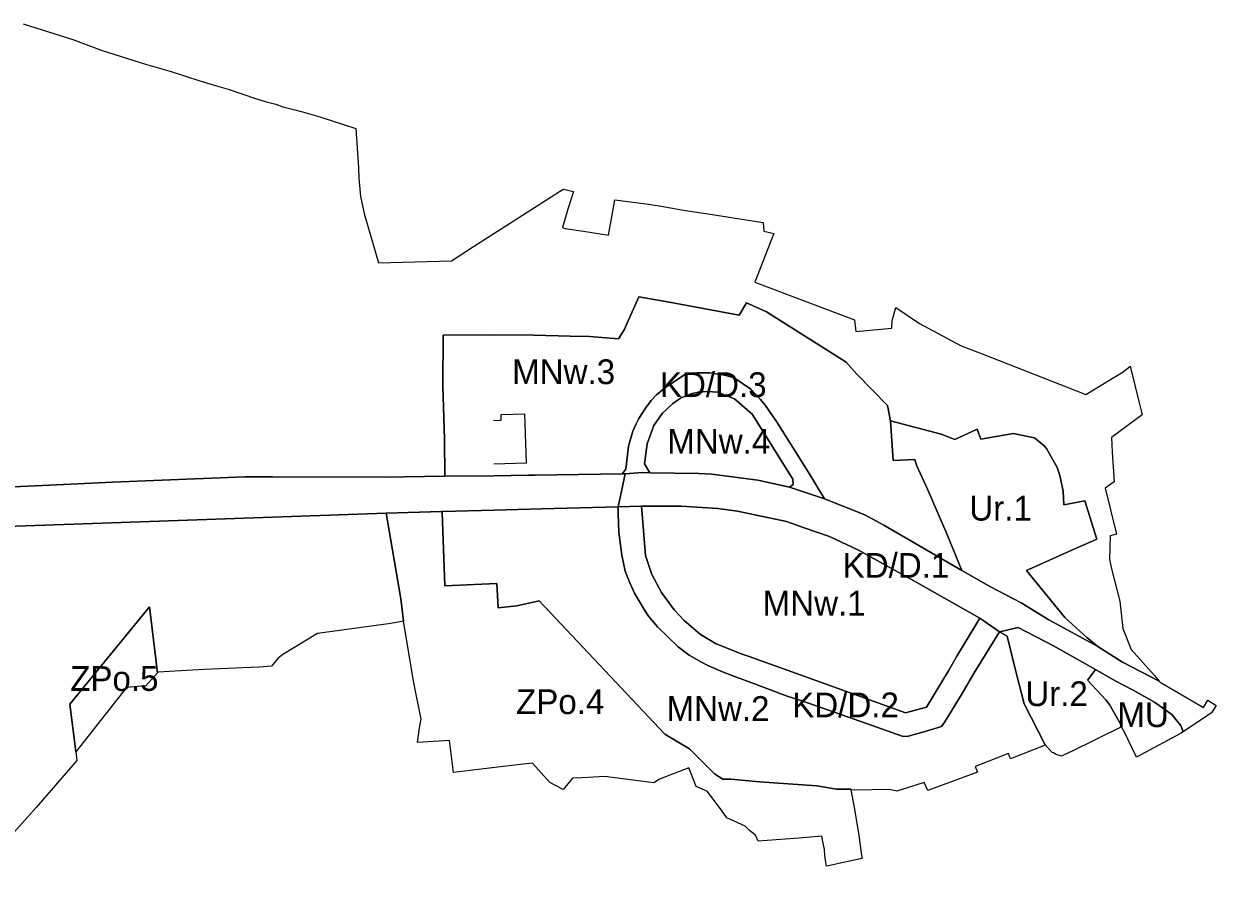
# Model space of a CAD drawing. Extents: x 7418114 to 7422197, y 5546299 to 5548348.
# Drawn here: x 7421715.4 to 7422197, y 5546763.3 to 5547110.1 of the extents above; entities that cross this region are included whole.
import ezdxf

# ---------------------------------------------------------------- set-up
doc = ezdxf.new("R2010")
doc.units = 0
for name, color, linetype in [('linie_rozgraniczajace', 7, 'Continuous'), ('linie_zabudowy_nieprzekraczalne', 7, 'Continuous'), ('oznaczenia_przeznaczen', 7, 'Continuous')]:
    doc.layers.add(name, color=color, linetype=linetype)

msp = doc.modelspace()

# ---------------------------------------------------------------- linework, layer by layer
at = {"layer": 'linie_rozgraniczajace'}
for points in [[(7421715.19, 5547110.07), (7421735.26, 5547103.68), (7421747.03, 5547099.34), (7421764.54, 5547093.8), (7421774.97, 5547090.79), (7421780.67, 5547088.99), (7421786.52, 5547087.08), (7421792.25, 5547085.24), (7421798.03, 5547083.67), (7421803.83, 5547081.68), (7421808.99, 5547079.88), (7421812.1, 5547078.95), (7421813.49, 5547078.58), (7421817.24, 5547077.57), (7421820.04, 5547076.58), (7421824.91, 5547075.26), (7421827.94, 5547074.48), (7421833.69, 5547072.95), (7421835.44, 5547072.38), (7421844.54, 5547069.37), (7421849.52, 5547067.79), (7421850.55, 5547051.83), (7421850.77, 5547047.76), (7421851.41, 5547040.3), (7421852.86, 5547033.4), (7421858.74, 5547013.44), (7421888.2, 5547014.28), (7421897.07, 5547020.04)], [(7421897.07, 5547020.04), (7421911.62, 5547029.42), (7421931.86, 5547042.32), (7421933.39, 5547043.29), (7421937.49, 5547042.38), (7421936.43, 5547038.94), (7421935.17, 5547035.15), (7421933, 5547027.75), (7421934.1, 5547027.4), (7421941.55, 5547026.29), (7421951.54, 5547024.62), (7421952.9, 5547032.08), (7421954.14, 5547038.9), (7421967.7, 5547037.24), (7421972.82, 5547036.39), (7421982.68, 5547034.62), (7421992.7, 5547033.12), (7422014.12, 5547029.86), (7422014.37, 5547026.28), (7422018.44, 5547025.37), (7422015.9, 5547019.13), (7422010.73, 5547005.69), (7422051.01, 5546990.53), (7422051.52, 5546985.79), (7422065.98, 5546987.12), (7422066.17, 5546990.19), (7422067.67, 5546995.47), (7422077.27, 5546988.94), (7422094.05, 5546979.99), (7422102.49, 5546976.78), (7422144.36, 5546960.37), (7422159.45, 5546969.45), (7422162.35, 5546971.73), (7422166.07, 5546956.41), (7422167.16, 5546952.08), (7422154.72, 5546942.96), (7422155.09, 5546937.03), (7422155.79, 5546925.05), (7422152.15, 5546922.44), (7422156.85, 5546903.88), (7422154.17, 5546903.2), (7422153.9, 5546893.59), (7422154.96, 5546889.37), (7422158.12, 5546876.77), (7422159.36, 5546865.74), (7422162.76, 5546857.26), (7422172.17, 5546846.8), (7422174.04, 5546844.51), (7422159.21, 5546852.2), (7422157.05, 5546853.55), (7422149.22, 5546858.49), (7422144.87, 5546862.15), (7422135.86, 5546870.24), (7422120.42, 5546889.14), (7422140.23, 5546898.1), (7422148.84, 5546901.92), (7422144.06, 5546917.41), (7422135.53, 5546915.66), (7422135.19, 5546921.31), (7422133.87, 5546927.64), (7422132.8, 5546930.77), (7422128.54, 5546938.52), (7422127.52, 5546939.58), (7422123.71, 5546942.81), (7422114.99, 5546944.51), (7422102, 5546942.21), (7422100.45, 5546946.35), (7422091.48, 5546942.18), (7422085.94, 5546944.22), (7422065.54, 5546949.61), (7422064.29, 5546955.86), (7422051.86, 5546968.57), (7422047.66, 5546973.4), (7422015.45, 5546993.74), (7422007.31, 5546997.33), (7422004.42, 5546992.34), (7421976.93, 5546997.45), (7421963.83, 5546999.72), (7421957.96, 5546986.4), (7421955.65, 5546982.86), (7421943.87, 5546983.7), (7421936.15, 5546983.89), (7421921.42, 5546984.29), (7421905.01, 5546984.42), (7421884.8, 5546984.3), (7421884.71, 5546963.86), (7421885.39, 5546942.06), (7421885.53, 5546927.25), (7421861, 5546926.89), (7421815.86, 5546926.99), (7421811.95, 5546927), (7421804.71, 5546927.01), (7421751.26, 5546924.91), (7421723.02, 5546923.6), (7421666.87, 5546920.97)], [(7421666.87, 5546920.97), (7421723.02, 5546923.6), (7421751.26, 5546924.91), (7421804.71, 5546927.01), (7421811.95, 5546927), (7421815.86, 5546926.99), (7421861, 5546926.89), (7421885.53, 5546927.25), (7421905.32, 5546927.49), (7421919.22, 5546927.66), (7421921.92, 5546927.77), (7421957.06, 5546928.27), (7421958.26, 5546928.29), (7421955.48, 5546914.95), (7421924.59, 5546914.1), (7421905.44, 5546913.59), (7421884.55, 5546913.01), (7421884.13, 5546913), (7421861.75, 5546912.42), (7421762.38, 5546908.91), (7421681.35, 5546906.04)], [(7421681.35, 5546906.04), (7421762.38, 5546908.91), (7421861.75, 5546912.42), (7421867.69, 5546877.79), (7421868.77, 5546868.77), (7421863.64, 5546867.76), (7421834.05, 5546863.7), (7421819.99, 5546855.19), (7421818, 5546853.69), (7421815.41, 5546850.55), (7421810.4, 5546850.09), (7421788.3, 5546849.19), (7421774.14, 5546848.4), (7421769.64, 5546848.17), (7421769.36, 5546847.85), (7421766.21, 5546874.51), (7421749.24, 5546853.73), (7421734.08, 5546835.17), (7421736.3, 5546817.18), (7421736.42, 5546815.98), (7421736.78, 5546812.38), (7421720.39, 5546793.42), (7421693.4, 5546763.27)]]:
    msp.add_lwpolyline(points, dxfattribs=at)
for points in [[(7421885.53, 5546927.25), (7421885.39, 5546942.06), (7421884.71, 5546963.86), (7421884.8, 5546984.3), (7421905.01, 5546984.42), (7421921.42, 5546984.29), (7421936.15, 5546983.89), (7421943.87, 5546983.7), (7421955.65, 5546982.86), (7421957.96, 5546986.4), (7421963.83, 5546999.72), (7421976.93, 5546997.45), (7422004.42, 5546992.34), (7422007.31, 5546997.33), (7422015.45, 5546993.74), (7422047.66, 5546973.4), (7422051.86, 5546968.57), (7422064.29, 5546955.86), (7422065.54, 5546949.61), (7422066.59, 5546933.64), (7422075.28, 5546933.99), (7422076.07, 5546931.82), (7422080.42, 5546922.07), (7422088.24, 5546904.05), (7422094.35, 5546889.13), (7422062.85, 5546907.46), (7422055.07, 5546911.65), (7422038.9, 5546918.1), (7422034.98, 5546924.58), (7422032.22, 5546929.09), (7422019.52, 5546949.34), (7422014.85, 5546955.96), (7422013.03, 5546958.33), (7422009.08, 5546962.43), (7422002.39, 5546967.06), (7421998.44, 5546968.14), (7421992.36, 5546969.05), (7421987.29, 5546969.05), (7421982.32, 5546968.25), (7421974.74, 5546963.27), (7421971, 5546960.21), (7421968.81, 5546957.94), (7421966.49, 5546954.77), (7421963.82, 5546950.58), (7421962.74, 5546948.45), (7421961.43, 5546945.48), (7421959.74, 5546939.4), (7421958.58, 5546930.2), (7421957.06, 5546928.27), (7421921.92, 5546927.77), (7421919.22, 5546927.66), (7421905.32, 5546927.49)], [(7421957.06, 5546928.27), (7421958.58, 5546930.2), (7421959.74, 5546939.4), (7421961.43, 5546945.48), (7421962.74, 5546948.45), (7421963.82, 5546950.58), (7421966.49, 5546954.77), (7421968.81, 5546957.94), (7421971, 5546960.21), (7421974.74, 5546963.27), (7421982.32, 5546968.25), (7421987.29, 5546969.05), (7421992.36, 5546969.05), (7421998.44, 5546968.14), (7422002.39, 5546967.06), (7422009.08, 5546962.43), (7422013.03, 5546958.33), (7422014.85, 5546955.96), (7422019.52, 5546949.34), (7422032.22, 5546929.09), (7422034.98, 5546924.58), (7422038.9, 5546918.1), (7422024.69, 5546922.93), (7422026.25, 5546923.99), (7422026.07, 5546926.09), (7422009.59, 5546952.34), (7422002.43, 5546958.55), (7421995.56, 5546961.19), (7421991.65, 5546961.53), (7421987.84, 5546961.29), (7421985.03, 5546960.56), (7421980.67, 5546958.82), (7421977.41, 5546956.52), (7421973.25, 5546952.57), (7421969.94, 5546947.73), (7421967.24, 5546940.31), (7421966.1, 5546932.3), (7421968.33, 5546928.7), (7421965.2, 5546928.74), (7421958.26, 5546928.29)], [(7421966.1, 5546932.3), (7421967.24, 5546940.31), (7421969.94, 5546947.73), (7421973.25, 5546952.57), (7421977.41, 5546956.52), (7421980.67, 5546958.82), (7421985.03, 5546960.56), (7421987.84, 5546961.29), (7421991.65, 5546961.53), (7421995.56, 5546961.19), (7422002.43, 5546958.55), (7422009.59, 5546952.34), (7422026.07, 5546926.09), (7422026.25, 5546923.99), (7422024.69, 5546922.93), (7422011.87, 5546925.71), (7421993.36, 5546928.16), (7421988.14, 5546928.45), (7421968.33, 5546928.7)], [(7422065.54, 5546949.61), (7422085.94, 5546944.22), (7422091.48, 5546942.18), (7422100.45, 5546946.35), (7422102, 5546942.21), (7422114.99, 5546944.51), (7422123.71, 5546942.81), (7422127.52, 5546939.58), (7422128.54, 5546938.52), (7422132.8, 5546930.77), (7422133.87, 5546927.64), (7422135.19, 5546921.31), (7422135.53, 5546915.66), (7422144.06, 5546917.41), (7422148.84, 5546901.92), (7422140.23, 5546898.1), (7422120.42, 5546889.14), (7422135.86, 5546870.24), (7422144.87, 5546862.15), (7422149.22, 5546858.49), (7422129.52, 5546869.21), (7422118.29, 5546876.09), (7422105.89, 5546882.57), (7422094.35, 5546889.13), (7422088.24, 5546904.05), (7422080.42, 5546922.07), (7422076.07, 5546931.82), (7422075.28, 5546933.99), (7422066.59, 5546933.64)], [(7421955.48, 5546914.95), (7421958.26, 5546928.29), (7421965.2, 5546928.74), (7421968.33, 5546928.7), (7421988.14, 5546928.45), (7421993.36, 5546928.16), (7422011.87, 5546925.71), (7422024.69, 5546922.93), (7422038.9, 5546918.1), (7422055.07, 5546911.65), (7422062.85, 5546907.46), (7422094.35, 5546889.13), (7422105.89, 5546882.57), (7422118.29, 5546876.09), (7422129.52, 5546869.21), (7422149.22, 5546858.49), (7422157.05, 5546853.55), (7422159.21, 5546852.2), (7422174.04, 5546844.51), (7422174.36, 5546844.11), (7422191.89, 5546833.82), (7422193.62, 5546836.76), (7422197.04, 5546834.68), (7422195.22, 5546831.64), (7422183.68, 5546824.01), (7422182.73, 5546826.61), (7422181.24, 5546828.3), (7422179.22, 5546830.92), (7422177.28, 5546832.41), (7422176.29, 5546833.08), (7422172.17, 5546835.94), (7422163.52, 5546840.9), (7422156.22, 5546844.6), (7422148.24, 5546849.22), (7422131.28, 5546858.78), (7422117.11, 5546866.21), (7422109.57, 5546864.41), (7422101.54, 5546869.87), (7422076.14, 5546884.34), (7422052.55, 5546897.45), (7422040.91, 5546902.9), (7422030.58, 5546906.39), (7422023.56, 5546908.97), (7422003.72, 5546913.17), (7421995.77, 5546914.26), (7421980.92, 5546915.18), (7421964.98, 5546915.2), (7421964.64, 5546915.2)], [(7421861.75, 5546912.42), (7421884.13, 5546913), (7421884.55, 5546913.01), (7421884.47, 5546912.63), (7421885.46, 5546882.98), (7421906.55, 5546883.91), (7421907.06, 5546874.16), (7421914.57, 5546874.94), (7421923.55, 5546876.97), (7421974.35, 5546823.04), (7421984.29, 5546817.2), (7421994.44, 5546807.03), (7421997.75, 5546804.94), (7422000.96, 5546804.88), (7422012.54, 5546803.79), (7422035.77, 5546802.14), (7422043.73, 5546800.8), (7422049.42, 5546800.89), (7422049.48, 5546800.62), (7422050.78, 5546793.46), (7422052.67, 5546782.21), (7422053.84, 5546774.02), (7422053.99, 5546772.86), (7422050.78, 5546772.18), (7422040.95, 5546770.01), (7422039.64, 5546769.77), (7422039.22, 5546772.22), (7422039.01, 5546774.05), (7422038.78, 5546776.42), (7422038.27, 5546779.06), (7422037.78, 5546781.85), (7422030.24, 5546781.15), (7422012.03, 5546779.86), (7422010.93, 5546782.24), (7422008.6, 5546784.2), (7422006.74, 5546785.85), (7421999.45, 5546789.24), (7421997.27, 5546792.42), (7421993.89, 5546796.85), (7421991.55, 5546799.89), (7421987.03, 5546801.96), (7421984.01, 5546809.46), (7421972.2, 5546804.83), (7421969.94, 5546803.44), (7421954.13, 5546805.43), (7421950.31, 5546805.91), (7421940.79, 5546805.39), (7421937.02, 5546805.31), (7421933.25, 5546800.72), (7421927.89, 5546803.57), (7421920.96, 5546811.4), (7421911.33, 5546810.26), (7421889.05, 5546807.52), (7421887.4, 5546820.54), (7421874.42, 5546819.64), (7421875.28, 5546825.6), (7421875.95, 5546829.15), (7421872.97, 5546843.81), (7421868.77, 5546868.77), (7421867.69, 5546877.79)], [(7421885.46, 5546882.98), (7421884.47, 5546912.63), (7421884.55, 5546913.01), (7421905.44, 5546913.59), (7421924.59, 5546914.1), (7421955.48, 5546914.95), (7421955.51, 5546912.07), (7421955.73, 5546904.65), (7421957, 5546895.33), (7421958.38, 5546888.88), (7421960.23, 5546884.17), (7421962.12, 5546879.99), (7421966.05, 5546873.41), (7421967.81, 5546870.72), (7421971.44, 5546866.44), (7421979.73, 5546858.35), (7421984.2, 5546855.05), (7421989.14, 5546852.18), (7421991.68, 5546850.81), (7421997.69, 5546848.23), (7422002.87, 5546846.25), (7422007.39, 5546844.66), (7422023.76, 5546838.45), (7422030.14, 5546836.34), (7422055.81, 5546827.4), (7422070.17, 5546822.25), (7422072.19, 5546822.18), (7422079.95, 5546824.23), (7422086.04, 5546826.18), (7422087.44, 5546828.03), (7422094.43, 5546839.55), (7422099.34, 5546847.9), (7422109.57, 5546864.41), (7422112.58, 5546862.71), (7422116.34, 5546847.3), (7422119.48, 5546835.31), (7422127.95, 5546818.69), (7422128.02, 5546818.57), (7422114.03, 5546813.04), (7422113.11, 5546815.23), (7422099.7, 5546809.95), (7422100.62, 5546807.77), (7422080.62, 5546800.28), (7422079.1, 5546803.56), (7422068.12, 5546800.05), (7422065.03, 5546800.76), (7422051.14, 5546800.47), (7422049.48, 5546800.62), (7422049.42, 5546800.89), (7422043.73, 5546800.8), (7422035.77, 5546802.14), (7422012.54, 5546803.79), (7422000.96, 5546804.88), (7421997.75, 5546804.94), (7421994.44, 5546807.03), (7421984.29, 5546817.2), (7421974.35, 5546823.04), (7421923.55, 5546876.97), (7421914.57, 5546874.94), (7421907.06, 5546874.16), (7421906.55, 5546883.91)], [(7421955.73, 5546904.65), (7421955.51, 5546912.07), (7421955.48, 5546914.95), (7421964.64, 5546915.2), (7421964.98, 5546915.2), (7421965.19, 5546911.91), (7421966.6, 5546895.21), (7421969.04, 5546887.62), (7421973.03, 5546880.35), (7421978.07, 5546873.3), (7421982.11, 5546868.94), (7421988.77, 5546863.4), (7421995.15, 5546859.51), (7422005.59, 5546855.34), (7422007.96, 5546854.6), (7422025.65, 5546848.25), (7422028.95, 5546847.03), (7422054.12, 5546837.97), (7422071.59, 5546831.72), (7422080.07, 5546833.99), (7422088.96, 5546848.59), (7422092.36, 5546854.54), (7422100, 5546867.3), (7422101.54, 5546869.87), (7422109.57, 5546864.41), (7422099.34, 5546847.9), (7422094.43, 5546839.55), (7422087.44, 5546828.03), (7422086.04, 5546826.18), (7422079.95, 5546824.23), (7422072.19, 5546822.18), (7422070.17, 5546822.25), (7422055.81, 5546827.4), (7422030.14, 5546836.34), (7422023.76, 5546838.45), (7422007.39, 5546844.66), (7422002.87, 5546846.25), (7421997.69, 5546848.23), (7421991.68, 5546850.81), (7421989.14, 5546852.18), (7421984.2, 5546855.05), (7421979.73, 5546858.35), (7421971.44, 5546866.44), (7421967.81, 5546870.72), (7421966.05, 5546873.41), (7421962.12, 5546879.99), (7421960.23, 5546884.17), (7421958.38, 5546888.88), (7421957, 5546895.33)], [(7421964.98, 5546915.2), (7421980.92, 5546915.18), (7421995.77, 5546914.26), (7422003.72, 5546913.17), (7422023.56, 5546908.97), (7422030.58, 5546906.39), (7422040.91, 5546902.9), (7422052.55, 5546897.45), (7422076.14, 5546884.34), (7422101.54, 5546869.87), (7422100, 5546867.3), (7422092.36, 5546854.54), (7422088.96, 5546848.59), (7422080.07, 5546833.99), (7422071.59, 5546831.72), (7422054.12, 5546837.97), (7422028.95, 5546847.03), (7422025.65, 5546848.25), (7422007.96, 5546854.6), (7422005.59, 5546855.34), (7421995.15, 5546859.51), (7421988.77, 5546863.4), (7421982.11, 5546868.94), (7421978.07, 5546873.3), (7421973.03, 5546880.35), (7421969.04, 5546887.62), (7421966.6, 5546895.21), (7421965.19, 5546911.91)], [(7421734.08, 5546835.17), (7421749.24, 5546853.73), (7421766.21, 5546874.51), (7421769.36, 5546847.85), (7421764.67, 5546842.66), (7421756.88, 5546841.97), (7421736.42, 5546815.98), (7421736.3, 5546817.18)], [(7422109.57, 5546864.41), (7422117.11, 5546866.21), (7422131.28, 5546858.78), (7422148.24, 5546849.22), (7422147.97, 5546848.84), (7422147.23, 5546847.76), (7422145.01, 5546844.93), (7422152.42, 5546836.88), (7422154, 5546835.05), (7422155.76, 5546831.92), (7422159.06, 5546826.09), (7422158.85, 5546825.99), (7422158.83, 5546826.02), (7422138.35, 5546815.96), (7422138.3, 5546815.94), (7422138.25, 5546815.91), (7422134.61, 5546814.22), (7422132.36, 5546814.87), (7422131.35, 5546815.56), (7422130.75, 5546815.66), (7422128.13, 5546818.62), (7422128.02, 5546818.57), (7422127.95, 5546818.69), (7422119.48, 5546835.31), (7422116.34, 5546847.3), (7422112.58, 5546862.71)], [(7422145.01, 5546844.93), (7422147.23, 5546847.76), (7422147.97, 5546848.84), (7422148.24, 5546849.22), (7422156.22, 5546844.6), (7422163.52, 5546840.9), (7422172.17, 5546835.94), (7422176.29, 5546833.08), (7422177.28, 5546832.41), (7422179.22, 5546830.92), (7422181.24, 5546828.3), (7422182.73, 5546826.61), (7422183.68, 5546824.01), (7422182.68, 5546823.34), (7422164.9, 5546813.82), (7422159.94, 5546824.18), (7422158.85, 5546825.99), (7422159.06, 5546826.09), (7422155.76, 5546831.92), (7422154, 5546835.05), (7422152.42, 5546836.88)]]:
    msp.add_lwpolyline(points, close=True, dxfattribs=at)
at = {"layer": 'linie_zabudowy_nieprzekraczalne'}
for points in [[(7421905.2, 5546949.85), (7421908.2, 5546949.93), (7421908.19, 5546952.07)], [(7421917.83, 5546952.32), (7421908.19, 5546952.07)], [(7421918.51, 5546932.68), (7421917.83, 5546952.32)], [(7421905.29, 5546932.34), (7421918.51, 5546932.68)]]:
    msp.add_lwpolyline(points, dxfattribs=at)

# ---------------------------------------------------------------- texts
at = {"layer": 'oznaczenia_przeznaczen'}
for s, p in [('MNw.3', (7421912.66, 5546964.49)), ('KD/D.3', (7421972.36, 5546959.28)), ('MNw.4', (7421975.33, 5546936.34)), ('Ur.1', (7422097.34, 5546909.37)), ('KD/D.1', (7422046.16, 5546886.26)), ('MNw.1', (7422013.85, 5546870.98)), ('ZPo.5', (7421734.15, 5546840.55)), ('ZPo.4', (7421914.25, 5546831.18)), ('Ur.2', (7422119.96, 5546834.4)), ('MNw.2', (7421975.02, 5546828.42)), ('KD/D.2', (7422025.8, 5546829.9)), ('MU', (7422157.13, 5546825.93))]:
    msp.add_text(s, height=10, dxfattribs=at).set_placement(p)

doc.saveas('drawing.dxf')
